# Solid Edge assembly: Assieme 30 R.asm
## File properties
Title: LAVABO BUCKET 30 R
Author: DESYS
Template: Iso Assembly.asm
Last saved by: PIM_1
Revision: 6
Application: Solid Edge
Tipo di contenuto documento: 1
Document Number: 8802
Revision: 0
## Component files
Lavabo Bucket 30-R.par
Portasciugamano Bucket 30.par
Perno filettato.par
Boccola portaasciugamani.par
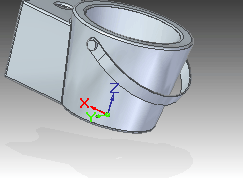
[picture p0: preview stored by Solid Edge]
